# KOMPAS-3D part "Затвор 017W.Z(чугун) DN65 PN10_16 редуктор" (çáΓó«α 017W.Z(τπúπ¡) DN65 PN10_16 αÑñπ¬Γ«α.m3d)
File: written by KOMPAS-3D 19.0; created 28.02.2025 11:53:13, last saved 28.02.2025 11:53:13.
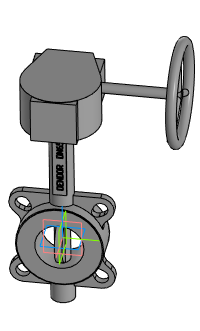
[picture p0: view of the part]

Document properties: Автор: Евгений; Полное имя файла: Затвор 017W.Z(чугун) DN65 PN10_16 редуктор.a3d

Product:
- Part/product: Затвор 017W.Z(чугун) DN65 PN10_16 редуктор
    Масса: 10.3717

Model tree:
1. Операция без истории:1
